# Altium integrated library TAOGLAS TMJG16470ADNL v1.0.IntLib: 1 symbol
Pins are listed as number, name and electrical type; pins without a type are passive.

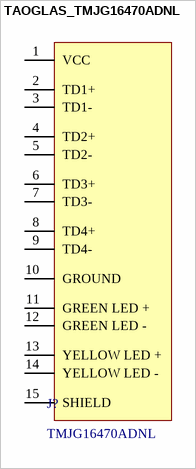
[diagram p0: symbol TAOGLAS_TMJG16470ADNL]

## TAOGLAS_TMJG16470ADNL
designator J?, comment TMJG16470ADNL
RJ45 connector with integrated magnetics 1G Base-T Single Port Tab-UP with right angle THT mount and LEDs; ComponentLibStatus: Created; MFG: Taoglas; Temp_High: +85C; Temp_Low: -40C
footprint TAOGLAS_TMJG16470ADNL (RJ45 connector with integrated magnetics 1G Base-T Single Port Tab-UP with right angle THT mount and LEDs)
pins: 1 VCC, 2 TD1+, 3 TD1-, 4 TD2+, 5 TD2-, 6 TD3+, 7 TD3-, 8 TD4+, 9 TD4-, 10 GROUND, 11 GREEN LED +, 12 GREEN LED -, 13 YELLOW LED +, 14 YELLOW LED -, 15 SHIELD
